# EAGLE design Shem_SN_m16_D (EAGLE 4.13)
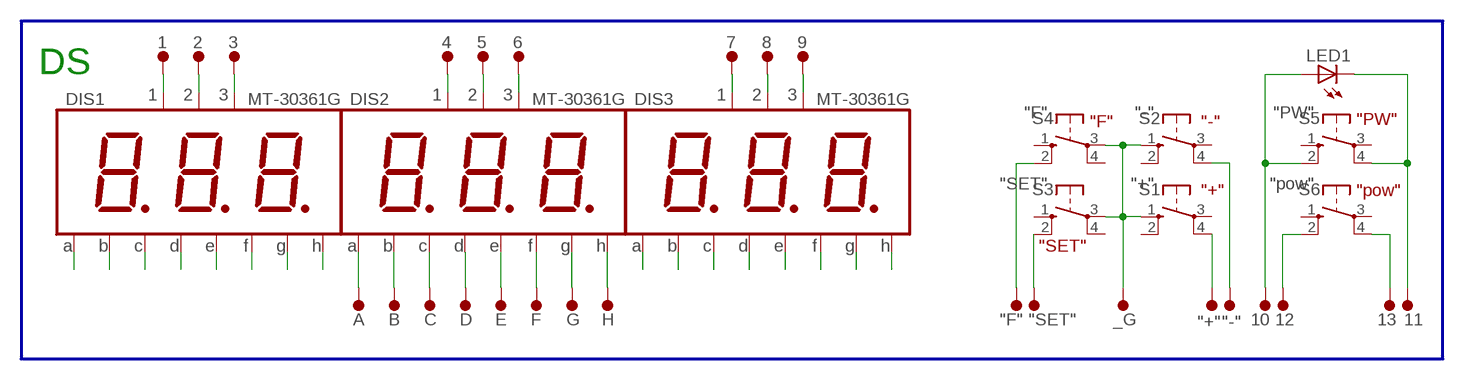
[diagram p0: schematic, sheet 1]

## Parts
1  2,0/0,8  [2,0/0,8]
2  2,0/0,8  [2,0/0,8]
3  2,0/0,8  [2,0/0,8]
4  2,0/0,8  [2,0/0,8]
5  2,0/0,8  [2,0/0,8]
6  2,0/0,8  [2,0/0,8]
7  2,0/0,8  [2,0/0,8]
8  2,0/0,8  [2,0/0,8]
9  2,0/0,8  [2,0/0,8]
10  2,0/0,8  [2,0/0,8]
11  2,0/0,8  [2,0/0,8]
12  2,0/0,8  [2,0/0,8]
13  2,0/0,8  [2,0/0,8]
"+"  2,0/0,8  [2,0/0,8]
"-"  2,0/0,8  [2,0/0,8]
"F"  2,0/0,8  [2,0/0,8]
"SET"  2,0/0,8  [2,0/0,8]
_G  2,0/0,8  [2,0/0,8]
A  2,0/0,8  [2,0/0,8]
B  2,0/0,8  [2,0/0,8]
C  2,0/0,8  [2,0/0,8]
D  2,0/0,8  [2,0/0,8]
DIS1  MT-30361G  MT-30361  [MT_]
DIS2  MT-30361G  MT-30361  [MT_]
DIS3  MT-30361G  MT-30361  [MT_]
E  2,0/0,8  [2,0/0,8]
F  2,0/0,8  [2,0/0,8]
G  2,0/0,8  [2,0/0,8]
H  2,0/0,8  [2,0/0,8]
LED1  LED3MM  [LED3MM]
S1  "+"  10-XX  [B3F-10XX]
S2  "-"  10-XX  [B3F-10XX]
S3  "SET"  10-XX  [B3F-10XX]
S4  "F"  10-XX  [B3F-10XX]
S5  "PW"  10-XX  [B3F-10XX]
S6  "pow"  10-XX  [B3F-10XX]

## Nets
A: A.1(P) DIS1.A DIS2.A DIS3.A
B: B.1(P) DIS1.B DIS2.B DIS3.B
C: C.1(P) DIS1.C DIS2.C DIS3.C
D: D.1(P) DIS1.D DIS2.D DIS3.D
E: DIS1.E DIS2.E DIS3.E E.1(P)
F: DIS1.F DIS2.F DIS3.F F.1(P)
G: DIS1.G DIS2.G DIS3.G G.1(P)
H: DIS1.H DIS2.H DIS3.H H.1(P)
I1: 1.1(P) DIS1.1
I2: 2.1(P) DIS1.2
I3: 3.1(P) DIS1.3
I4: 4.1(P) DIS2.1
I5: 5.1(P) DIS2.2
I6: 6.1(P) DIS2.3
I7: 7.1(P) DIS3.1
I8: 8.1(P) DIS3.2
I9: 9.1(P) DIS3.3
N$1: "+".1(P) S1.4(P1)
N$2: "-".1(P) S2.4(P1)
N$3: "SET".1(P) S3.2(S1)
N$4: 12.1(P) S6.2(S1)
N$5: _G.1(P) S1.1(S) S2.1(S) S3.3(P) S4.3(P)
N$6: 13.1(P) S6.4(P1)
N$7: 10.1(P) LED1.A S5.2(S1)
N$8: 11.1(P) LED1.K(C) S5.4(P1)
N$9: "F".1(P) S4.2(S1)
Unconnected: S1.2(S1) S1.3(P) S2.2(S1) S2.3(P) S3.1(S) S3.4(P1) S4.1(S) S4.4(P1) S5.1(S) S5.3(P) S6.1(S) S6.3(P)

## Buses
B$1

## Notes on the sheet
- DS
- "F" | "-" | "PW"
- "+" | "pow"
- "SET"

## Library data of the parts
1-13 "+" "-" "F" "SET" _G A B C D E F G H = wirepad:2,0/0,8: THROUGH-HOLE PAD
DIS1-DIS3 = display:MT-30361: LED DISPLAY 3 character 7 segment, decimal points right
LED1 = led:LED: LED
S1-S6 = switch-omron:10-XX: OMRON SWITCH

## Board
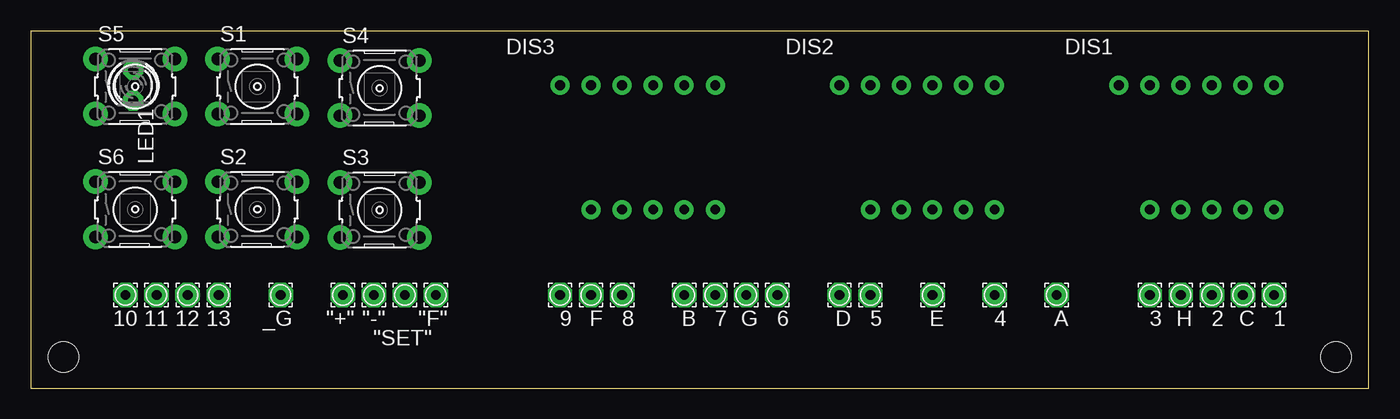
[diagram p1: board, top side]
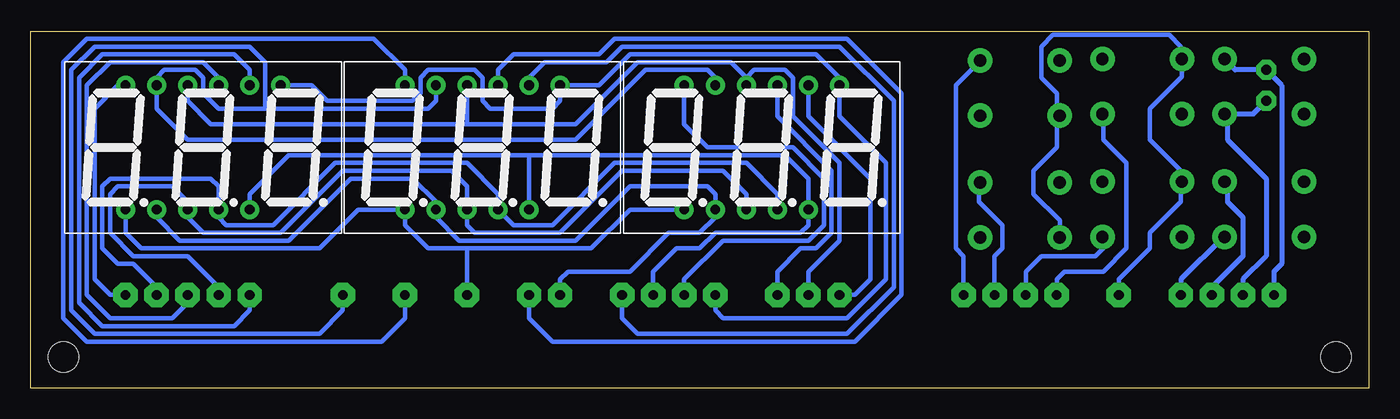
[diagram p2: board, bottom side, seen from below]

Size 109.52 x 29.2 mm. Coordinates in mm from the lower left corner, seen from the top.
Outline: 0,0 109.52,0
Outline: 109.52,0 109.52,29.2 0,29.2 0,0
Outline: 109.52,0 109.52,5.07
Outline: 0,5.07 0,0
Copper layers (1*16): Top 0.035mm / dielectric 1.5mm / Bottom 0.035mm
Design rules "default": minimum track width 14mil, minimum drill 24mil, track to track 14mil, track to pad 8mil, pad to pad 8mil, via to via 8mil, smd to smd 8mil, copper to edge 0mil, drill to drill 8mil, minimum pad ring 10mil, minimum via ring 8mil, stop-mask expansion 4mil, vias tented up to drill 0mil, thermal gap 10mil
Holes 2.5 mm at 2.69,2.53 106.83,2.53

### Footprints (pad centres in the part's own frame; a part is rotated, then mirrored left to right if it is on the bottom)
2,0/0,8 = drill 0.8 pad 2 octagon: 1 0,0
MT_ = drill 0.8 long: 1 -6.35,5.08; 2 1.27,5.08; 3 3.81,5.08; A -3.81,5.08; B 6.35,5.08; C 1.27,-5.08; D -3.81,-5.08; E -6.35,-5.08; F -1.27,5.08; G 3.81,-5.08; H -1.27,-5.08
LED3MM = drill 0.813 octagon: A -1.27,0; K 1.27,0
B3F-10XX = drill 1.016 long: 1 -3.251,2.261; 2 3.251,2.261; 3 -3.251,-2.261; 4 3.251,-2.261

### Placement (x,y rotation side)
1  101.75,7.62 180 top
2  96.67,7.62 180 top
3  91.59,7.62 180 top
4  78.89,7.62 180 top
5  68.73,7.62 180 top
6  61.11,7.62 180 top
7  56.03,7.62 180 top
8  48.41,7.62 180 top
9  43.33,7.62 180 top
10  7.77,7.62 180 top
11  10.31,7.62 180 top
12  12.85,7.62 180 top
13  15.39,7.62 180 top
"+"  25.55,7.62 180 top
"-"  28.09,7.62 180 top
"F"  33.17,7.62 180 top
"SET"  30.63,7.62 180 top
_G  20.47,7.62 180 top
A  83.97,7.62 180 top
B  53.49,7.62 180 top
C  99.21,7.62 180 top
D  66.19,7.62 180 top
DIS1  95.4,19.68 0 bottom
DIS2  72.54,19.68 0 bottom
DIS3  49.68,19.68 0 bottom
E  73.81,7.62 180 top
F  45.87,7.62 180 top
G  58.57,7.62 180 top
H  94.13,7.62 180 top
LED1  8.41,24.76 270 top
S1  18.56,24.66 0 top
S2  18.56,14.62 0 top
S3  28.56,14.56 0 top
S4  28.56,24.53 0 top
S5  8.56,24.66 0 top
S6  8.56,14.62 0 top

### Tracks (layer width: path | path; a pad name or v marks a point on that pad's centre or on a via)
A
  Bottom 0.356: DIS3.A 53.49,25.4 54.13,26.03 59.21,26.03 64.92,20.31 96.67,20.31 99.21,22.85 DIS1.A 99.21,25.4 98.58,26.03 96.04,26.03 95.4,25.4 95.4,24.12 94.13,22.85 90.32,22.85 | A.1 83.97,6.34 85.88,4.44 104.29,4.44 106.2,6.34 106.2,26.03 104.29,27.94 91.59,27.94 90.32,26.66 90.32,22.85 | DIS2.A 76.35,23.49 76.99,22.85 90.32,22.85
B
  Bottom 0.356: B.1 53.49,6.34 52.86,5.71 42.7,5.71 39.52,8.88 39.52,18.41 43.33,22.22 DIS3.B 43.33,25.4 45.24,27.3 60.48,27.3 63.02,24.76 DIS2.B 66.19,23.49 66.83,22.85 71.91,22.85 72.54,23.49 72.54,25.4 73.18,26.03 76.99,26.03 77.62,25.4 77.62,24.12 78.26,23.49 85.24,23.49 86.51,24.76 DIS1.B
C
  Bottom 0.356: DIS3.C 48.41,15.87 50.95,18.41 61.75,18.41 66.83,13.33 70,13.33 DIS2.C 71.27,15.87 73.81,18.41 84.61,18.41 89.69,13.33 93.5,13.33 94.13,13.97 DIS1.C 94.13,16.5 94.77,17.14 103.02,17.14 103.66,16.5 103.66,11.43 102.39,10.16 101.12,10.16 99.21,8.25 C.1
D
  Bottom 0.356: DIS1.D 99.21,13.97 97.31,12.06 88.42,12.06 83.34,17.14 78.26,17.14 76.35,15.23 DIS2.D 76.35,13.97 74.45,12.06 64.92,12.06 60.48,16.5 54.13,16.5 53.49,15.87 DIS3.D 53.49,13.97 54.76,12.69 57.3,12.69 60.48,9.52 65.56,9.52 66.19,8.88 D.1
E
  Bottom 0.356: DIS1.E 101.75,12.69 100.48,11.43 85.88,11.43 82.7,14.6 DIS2.E 78.89,13.33 76.99,11.43 73.81,11.43 | DIS3.E 60.48,14.6 63.65,11.43 73.81,11.43 | 73.81,11.43 E.1
F
  Bottom 0.356: 50.95,25.4 50.32,26.03 47.78,26.03 47.14,25.4 47.14,22.22 43.33,18.41 43.33,12.06 45.87,9.52 F.1 | 50.95,25.4 DIS3.F | 50.95,25.4 52.22,26.66 59.84,26.66 64.92,21.59 73.81,21.59 | 73.81,21.59 DIS2.F | 73.81,21.59 94.77,21.59 96.67,23.49 DIS1.F
G
  Bottom 0.356: DIS1.G 91.59,15.87 88.42,19.04 68.73,19.04 | 68.73,19.04 DIS2.G | 68.73,19.04 47.78,19.04 45.87,17.14 DIS3.G 45.87,13.33 46.51,12.69 53.49,12.69 54.76,11.43 56.67,11.43 58.57,9.52 G.1
H
  Bottom 0.356: DIS3.H 50.95,15.87 52.86,17.78 61.11,17.78 66.19,12.69 73.18,12.69 73.81,13.33 DIS2.H 73.81,16.5 75.08,17.78 83.97,17.78 89.05,12.69 95.4,12.69 96.67,13.97 DIS1.H 96.67,15.23 97.94,16.5 102.39,16.5 103.02,15.87 103.02,12.69 101.12,10.79 96.67,10.79 94.13,8.25 H.1
I1
  Bottom 0.356: DIS1.1 102.39,24.76 104.29,22.85 104.29,8.88 103.02,7.62 1.1
I2
  Bottom 0.356: 2.1 96.67,6.98 97.94,5.71 103.02,5.71 104.93,7.62 104.93,24.76 103.02,26.66 95.4,26.66 94.13,25.4 DIS1.2
I3
  Bottom 0.356: 3.1 91.59,6.34 92.86,5.07 103.66,5.07 105.56,6.98 105.56,25.4 103.66,27.3 92.86,27.3 91.59,26.03 DIS1.3
I4
  Bottom 0.356: 4.1 78.89,5.71 80.8,3.81 104.93,3.81 106.83,5.71 106.83,26.66 104.93,28.57 81.43,28.57 78.89,26.03 DIS2.1
I5
  Bottom 0.356: DIS2.2 71.27,26.03 70,27.3 63.02,27.3 61.75,28.57 42.7,28.57 38.25,24.12 38.25,7.62 42.06,3.81 66.83,3.81 68.73,5.71 5.1
I6
  Bottom 0.356: DIS2.3 68.73,25.4 67.46,26.66 62.38,26.66 61.11,27.94 43.33,27.94 38.89,23.49 38.89,8.25 42.7,4.44 59.84,4.44 61.11,5.71 6.1
I7
  Bottom 0.356: DIS3.1 56.03,21.59 54.13,19.68 47.14,19.68 44.6,17.14 44.6,13.33 45.87,12.06 52.86,12.06 56.03,8.88 7.1
I8
  Bottom 0.356: DIS3.2 48.41,22.22 43.97,17.78 43.97,12.69 45.24,11.43 46.51,11.43 48.41,9.52 8.1
I9
  Bottom 0.356: DIS3.3 45.87,22.22 40.79,17.14 40.79,8.88 42.06,7.62 9.1
N$1
  Bottom 0.356: "+".1 25.55,8.88 24.92,9.52 21.74,9.52 19.84,11.43 19.84,18.41 21.74,20.31 21.74,22.85 21.81,22.78 S1.4
N$2
  Bottom 0.356: "-".1 28.09,9.52 26.82,10.79 22.38,10.79 21.74,11.43 21.74,12.69 21.81,12.62 S2.4
N$3
  Bottom 0.356: "SET".1 30.63,10.79 30,11.43 30,13.33 31.9,15.23 31.9,16.5 31.81,16.59 S3.2
N$4
  Bottom 0.406: 12.1 12.85,8.25 10.31,10.79 10.31,13.97 11.58,15.23 11.58,16.5 11.81,16.74 S6.2
N$5
  Bottom 0.356: 25.55,22.22 25.55,19.68 27.46,17.78 27.46,15.87 25.31,13.72 S3.3 25.31,12.94 | 25.55,22.22 25.5,22.27 S4.3 | 25.55,22.22 25.55,24.12 26.82,25.4 26.82,27.94 25.87,28.89 16.34,28.89 15.39,27.94 15.39,26.66 15.31,26.75 S1.1 15.31,25.48 17.93,22.85 17.93,20.31 15.39,17.78 15.39,16.5 | _G.1 20.47,8.88 17.93,11.43 17.93,12.69 15.39,15.23 15.39,16.5 | 15.39,16.5 15.31,16.59 S2.1
N$6
  Bottom 0.406: S6.4 11.92,12.35 15.39,8.88 13.1
N$7
  Bottom 0.406: 10.1 7.77,9.52 7.14,10.16 7.14,24.76 LED1.A 10.95,26.03 11.81,26.9 S5.2
N$8
  Bottom 0.406: 11.1 10.31,8.88 8.41,10.79 8.41,17.14 11.58,20.31 11.58,22.22 11.77,22.4 S5.4 9.49,22.4 LED1.K
N$9
  Bottom 0.356: "F".1 33.17,10.79 33.81,11.43 33.81,24.76 31.81,26.75 S4.2

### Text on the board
Drills: 5mm | 5mm | 10mm | 10mm | 14mm | 30mm | 30mm | 14mm | 10mm | 10mm | 10mm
